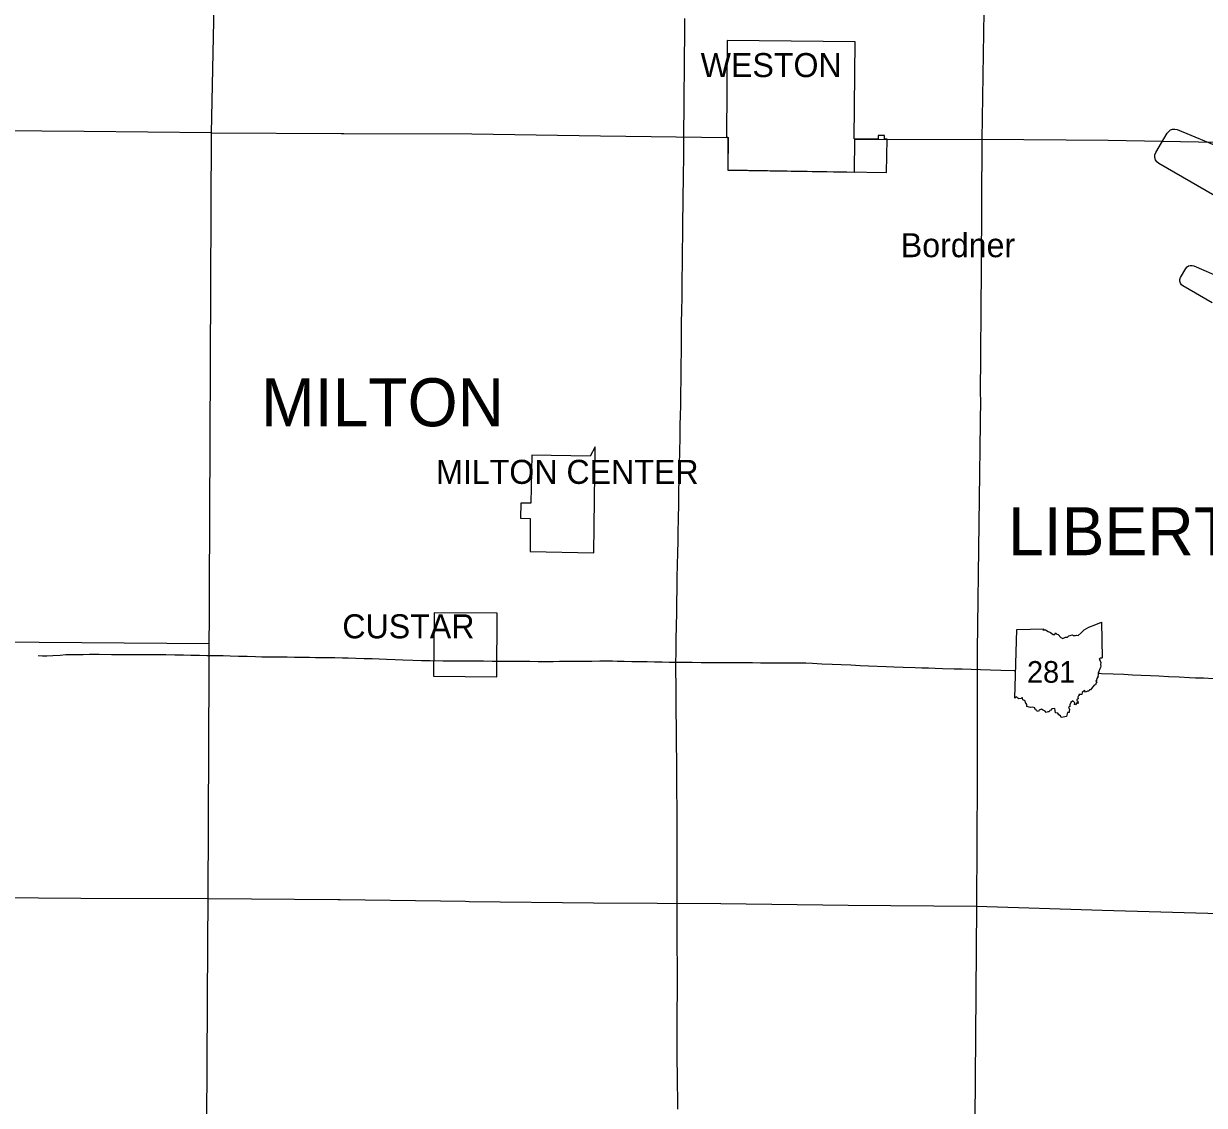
# Model space of a CAD drawing. Extents: x -232 to 448, y 619 to 1059.
# Drawn here: x 68.1 to 118.6, y 774.3 to 820.5 of the extents above; entities that cross this region are included whole.
import ezdxf

# ---------------------------------------------------------------- set-up
doc = ezdxf.new("R2010")
doc.units = 0
doc.layers.add('Default', color=7, linetype='Continuous')

msp = doc.modelspace()

# ---------------------------------------------------------------- linework, layer by layer
at = {"layer": 'Default'}
for p, q in [((104.623, 815.735), (104.617, 815.584)), ((104.9, 815.73), (104.623, 815.735)), ((104.897, 815.576), (104.9, 815.73)), ((104.617, 815.584), (103.599, 815.589)), ((105.003, 815.578), (104.897, 815.576)), ((104.979, 814.149), (105.003, 815.578)), ((110.457, 791.72), (110.539, 794.648)), ((110.457, 791.72), (110.539, 794.648))]:
    msp.add_line(p, q, dxfattribs=at)
for points in [[(109.26, 831.913), (109.194, 826.425), (109.132, 821.025), (109.053, 815.566)], [(76.168, 815.845), (76.27, 821.291)], [(96.36, 819.165), (96.361, 819.235), (96.366, 819.816), (96.37, 820.325), (96.373, 820.728)], [(103.636, 819.733), (98.172, 819.783), (98.153, 815.657)], [(103.599, 815.589), (103.636, 819.733)], [(96.326, 815.07), (96.329, 815.569), (96.332, 816.125), (96.337, 816.673), (96.345, 817.195), (96.347, 817.753), (96.354, 818.299), (96.355, 818.806), (96.36, 819.165)], [(76.168, 815.845), (70.724, 815.907), (65.304, 815.949), (59.876, 816.001), (54.446, 816.075), (54.399, 816.071), (49.027, 816.078), (48.986, 816.078), (43.453, 816.11)], [(76.015, 783.15), (76.168, 815.845)], [(76.168, 815.845), (81.699, 815.818), (81.812, 815.822), (87.28, 815.809), (92.763, 815.723), (98.167, 815.653), (98.218, 815.652), (98.2, 814.256), (103.614, 814.171), (103.632, 815.58), (109.053, 815.566)], [(98.153, 815.657), (98.21, 815.656)], [(98.21, 815.656), (98.21, 814.274)], [(120.275, 812.415), (116.605, 814.534), (116.52, 814.603), (116.46, 814.694), (116.432, 814.8), (116.438, 814.909), (116.477, 815.011), (116.955, 815.838), (117.099, 815.975), (117.194, 816.007), (117.294, 816.011), (117.391, 815.986), (121.228, 814.392)], [(109.053, 815.566), (109.022, 810.07), (108.982, 804.635), (108.986, 804.516), (108.919, 799.171), (108.846, 793.728), (108.845, 788.284), (108.821, 782.822)], [(141.903, 814.75), (138.372, 814.906), (136.423, 814.952), (130.937, 815.125), (125.356, 815.31), (119.857, 815.421), (114.444, 815.526), (109.053, 815.566)], [(96.308, 813.659), (96.309, 813.713), (96.313, 814.128), (96.32, 814.723), (96.326, 815.07)], [(98.21, 814.274), (104.979, 814.149)], [(95.988, 793.251), (95.995, 793.649), (96.004, 794.216), (96.013, 794.803), (96.024, 795.353), (96.033, 795.821), (96.043, 796.354), (96.048, 796.859), (96.061, 797.407), (96.069, 797.918), (96.078, 798.419), (96.086, 798.766), (96.097, 799.392), (96.109, 799.987), (96.118, 800.494), (96.128, 801.077), (96.141, 801.664), (96.153, 802.253), (96.164, 802.832), (96.173, 803.314), (96.183, 803.837), (96.195, 804.155), (96.198, 804.671), (96.208, 805.36), (96.214, 805.972), (96.224, 806.485), (96.23, 807.113), (96.234, 807.738), (96.242, 808.261), (96.252, 808.832), (96.254, 809.3), (96.26, 809.657), (96.265, 810.203), (96.273, 810.819), (96.278, 811.478), (96.287, 812.149), (96.297, 812.761), (96.303, 813.354), (96.308, 813.659)], [(118.887, 808.586), (117.633, 809.31), (117.569, 809.361), (117.525, 809.43), (117.504, 809.509), (117.508, 809.591), (117.537, 809.667), (117.765, 810.061), (117.812, 810.121), (117.874, 810.164), (117.946, 810.188), (118.022, 810.19), (118.095, 810.171), (119.276, 809.66)], [(92.33, 802.044), (89.838, 802.086), (89.799, 800.04), (89.368, 800.04), (89.356, 799.392), (89.768, 799.382), (89.766, 799.117), (89.768, 798.951), (89.764, 798.593), (89.768, 798.322), (89.76, 797.98)], [(89.76, 797.98), (92.485, 797.917), (92.542, 802.445)], [(92.542, 802.445), (92.33, 802.044)], [(85.667, 795.362), (85.646, 792.656)], [(85.646, 792.656), (88.341, 792.623), (88.358, 795.343)], [(88.358, 795.343), (85.667, 795.362)], [(110.539, 794.648), (111.675, 794.668), (111.657, 794.632), (111.765, 794.625), (111.879, 794.562), (111.975, 794.523), (112.093, 794.43), (112.163, 794.431), (112.193, 794.507), (112.247, 794.448), (112.311, 794.437), (112.422, 794.297), (112.513, 794.267), (112.623, 794.315), (112.705, 794.323), (112.765, 794.37), (112.921, 794.411), (112.964, 794.387), (113.047, 794.392), (113.088, 794.41), (113.16, 794.393), (113.287, 794.5), (113.417, 794.626), (113.618, 794.744), (113.918, 794.856), (114.155, 794.957), (114.189, 793.437)], [(110.539, 794.648), (111.675, 794.668), (111.657, 794.632), (111.765, 794.625), (111.879, 794.562), (111.975, 794.523), (112.093, 794.43), (112.163, 794.431), (112.193, 794.507), (112.247, 794.448), (112.311, 794.437), (112.422, 794.297), (112.513, 794.267), (112.623, 794.315), (112.705, 794.323), (112.765, 794.37), (112.921, 794.411), (112.964, 794.387), (113.047, 794.392), (113.088, 794.41), (113.16, 794.393), (113.287, 794.5), (113.417, 794.626), (113.618, 794.744), (113.918, 794.856), (114.155, 794.957), (114.189, 793.437)], [(59.717, 794.177), (76.066, 794.048)], [(68.765, 793.531), (68.946, 793.521), (69.124, 793.527), (69.39, 793.542), (69.694, 793.555), (69.947, 793.571), (70.165, 793.579), (70.34, 793.583), (70.677, 793.582), (70.955, 793.585), (71.37, 793.586), (71.889, 793.582), (72.377, 793.581), (72.847, 793.581), (73.333, 793.578), (73.758, 793.578), (74.217, 793.576), (74.594, 793.569), (74.972, 793.56), (75.273, 793.553), (75.648, 793.547), (75.968, 793.539), (76.269, 793.537), (76.665, 793.53), (76.96, 793.523), (77.313, 793.509), (77.686, 793.504), (78.034, 793.492), (78.313, 793.485), (78.373, 793.485)], [(78.373, 793.485), (78.574, 793.484), (78.828, 793.48), (78.861, 793.479)], [(78.861, 793.479), (79.095, 793.476), (79.392, 793.473), (79.71, 793.468), (79.726, 793.467)], [(79.726, 793.467), (80.015, 793.463), (80.348, 793.461), (80.602, 793.455), (80.881, 793.453), (81.074, 793.449)], [(81.074, 793.449), (81.123, 793.447), (81.42, 793.443), (81.748, 793.439), (81.996, 793.431), (82.328, 793.422), (82.685, 793.414), (83.025, 793.402), (83.322, 793.389), (83.636, 793.377), (83.999, 793.363), (84.327, 793.351), (84.759, 793.335), (85.124, 793.32), (85.499, 793.316), (86.047, 793.312), (86.486, 793.312), (86.916, 793.306), (87.353, 793.304), (87.774, 793.303), (88.145, 793.298), (88.547, 793.297), (88.943, 793.294), (89.353, 793.291), (89.753, 793.288), (90.11, 793.286), (90.472, 793.281), (90.749, 793.281), (91.018, 793.287), (91.363, 793.288), (91.712, 793.29), (92.023, 793.293), (92.399, 793.299), (92.742, 793.301), (93.058, 793.302), (93.283, 793.305), (93.474, 793.299), (93.781, 793.296), (94.107, 793.286), (94.45, 793.278), (94.755, 793.275), (95.081, 793.27), (95.399, 793.262), (95.707, 793.255), (95.988, 793.251)], [(96.047, 777.004), (96.046, 777.361), (96.045, 777.939), (96.048, 778.461), (96.05, 779.048), (96.05, 779.447), (96.052, 780.004), (96.052, 780.323), (96.046, 781.069), (96.044, 781.835), (96.045, 782.342), (96.04, 783.03), (96.044, 783.72), (96.042, 784.264), (96.042, 784.708), (96.04, 785.242), (96.039, 785.798), (96.035, 786.256), (96.037, 786.689), (96.036, 787.176), (96.033, 787.597), (96.031, 787.948), (96.029, 788.466), (96.024, 789.129), (96.017, 789.645), (96.013, 790.072), (96.008, 790.507), (96.002, 791.109), (95.998, 791.585), (95.995, 791.994), (95.994, 792.366), (95.987, 792.787), (95.984, 793.103), (95.988, 793.251)], [(95.988, 793.251), (96.295, 793.246), (96.685, 793.247), (97.072, 793.242), (97.405, 793.241), (97.698, 793.238), (98.045, 793.238), (98.387, 793.235), (98.699, 793.232), (99.035, 793.232), (99.261, 793.231), (99.595, 793.227), (99.958, 793.227), (100.288, 793.226), (100.586, 793.223), (101.047, 793.221), (101.533, 793.218)], [(101.533, 793.218), (101.816, 793.205), (102.224, 793.185), (102.665, 793.167), (103.05, 793.148), (103.462, 793.132), (103.857, 793.115), (104.216, 793.098), (104.958, 793.067), (105.296, 793.051), (105.689, 793.036), (106.203, 793.016), (106.494, 793.009), (106.769, 793.002), (107.056, 792.993), (107.372, 792.986), (107.873, 792.971), (108.216, 792.96), (108.589, 792.949), (108.987, 792.934), (109.414, 792.925), (109.86, 792.914), (110.435, 792.898), (110.503, 792.896)], [(114.189, 793.437), (114.154, 793.415), (114.1, 793.425), (114.063, 793.383), (114.108, 793.312), (114.13, 793.237), (114.111, 793.154), (114.13, 793.085), (114.117, 793.028), (114.083, 792.971), (114.071, 792.917), (114.042, 792.86), (114.044, 792.828), (114.016, 792.803), (114.021, 792.707), (114.007, 792.655), (114.012, 792.609), (113.967, 792.597), (113.977, 792.56), (113.949, 792.531), (113.955, 792.481), (113.923, 792.449), (113.954, 792.385), (113.929, 792.365), (113.908, 792.288), (113.85, 792.272), (113.734, 792.13), (113.694, 792.076), (113.648, 792.063), (113.623, 792.008), (113.566, 792.008), (113.481, 791.97), (113.426, 792.035), (113.329, 791.956), (113.318, 791.865), (113.196, 791.868), (113.2, 791.822), (113.173, 791.808), (113.148, 791.762), (113.163, 791.68), (113.105, 791.659), (113.112, 791.611), (113.149, 791.582), (113.165, 791.491), (113.104, 791.509), (113.055, 791.432), (113.003, 791.45), (113.02, 791.515), (112.934, 791.594), (112.852, 791.531), (112.809, 791.431), (112.808, 791.363), (112.747, 791.323), (112.787, 791.227), (112.779, 791.162), (112.781, 791.1), (112.704, 791.102), (112.658, 790.934)], [(114.189, 793.437), (114.154, 793.415), (114.1, 793.425), (114.063, 793.383), (114.108, 793.312), (114.13, 793.237), (114.111, 793.154), (114.13, 793.085), (114.117, 793.028), (114.083, 792.971), (114.071, 792.917), (114.042, 792.86), (114.044, 792.828), (114.016, 792.803), (114.021, 792.707), (114.007, 792.655), (114.012, 792.609), (113.967, 792.597), (113.977, 792.56), (113.949, 792.531), (113.955, 792.481), (113.923, 792.449), (113.954, 792.385), (113.929, 792.365), (113.908, 792.288), (113.85, 792.272), (113.734, 792.13), (113.694, 792.076), (113.648, 792.063), (113.623, 792.008), (113.566, 792.008), (113.481, 791.97), (113.426, 792.035), (113.329, 791.956), (113.318, 791.865), (113.196, 791.868), (113.2, 791.822), (113.173, 791.808), (113.148, 791.762), (113.163, 791.68), (113.105, 791.659), (113.112, 791.611), (113.149, 791.582), (113.165, 791.491), (113.104, 791.509), (113.055, 791.432), (113.003, 791.45), (113.02, 791.515), (112.934, 791.594), (112.852, 791.531), (112.809, 791.431), (112.808, 791.363), (112.747, 791.323), (112.787, 791.227), (112.779, 791.162), (112.781, 791.1), (112.704, 791.102), (112.658, 790.934)], [(114.059, 792.775), (114.154, 792.771), (114.663, 792.75), (115.11, 792.732), (115.483, 792.716), (115.857, 792.697), (116.245, 792.678), (116.608, 792.662), (117.014, 792.641), (117.478, 792.619), (117.913, 792.601), (118.172, 792.587), (118.514, 792.577), (118.923, 792.56)], [(112.658, 790.934), (112.526, 790.901), (112.433, 790.882), (112.401, 790.959), (112.335, 790.999), (112.292, 791.076), (112.198, 791.086), (112.175, 791.192), (112.165, 791.278), (112.036, 791.256), (112, 791.204), (111.954, 791.19), (111.928, 791.137), (111.865, 791.133), (111.798, 791.108), (111.754, 791.16), (111.644, 791.212), (111.595, 791.238), (111.492, 791.197), (111.47, 791.147), (111.387, 791.169), (111.368, 791.224), (111.318, 791.241), (111.307, 791.299), (111.201, 791.33), (111.12, 791.318), (110.976, 791.365), (110.968, 791.441), (110.919, 791.535), (110.893, 791.6), (110.803, 791.649), (110.784, 791.727), (110.755, 791.724), (110.729, 791.693), (110.628, 791.679), (110.588, 791.71), (110.531, 791.764), (110.457, 791.72)], [(112.658, 790.934), (112.526, 790.901), (112.433, 790.882), (112.401, 790.959), (112.335, 790.999), (112.292, 791.076), (112.198, 791.086), (112.175, 791.192), (112.165, 791.278), (112.036, 791.256), (112, 791.204), (111.954, 791.19), (111.928, 791.137), (111.865, 791.133), (111.798, 791.108), (111.754, 791.16), (111.644, 791.212), (111.595, 791.238), (111.492, 791.197), (111.47, 791.147), (111.387, 791.169), (111.368, 791.224), (111.318, 791.241), (111.307, 791.299), (111.201, 791.33), (111.12, 791.318), (110.976, 791.365), (110.968, 791.441), (110.919, 791.535), (110.893, 791.6), (110.803, 791.649), (110.784, 791.727), (110.755, 791.724), (110.729, 791.693), (110.628, 791.679), (110.588, 791.71), (110.531, 791.764), (110.457, 791.72)], [(76.015, 783.15), (70.577, 783.165), (65.14, 783.201), (59.652, 783.191), (54.113, 783.24), (48.623, 783.305), (43.396, 783.369)], [(75.834, 750.532), (76.007, 781.259), (76.015, 783.15)], [(108.821, 782.822), (103.347, 782.858), (97.913, 782.939), (92.468, 782.966), (87.167, 783.026), (87.011, 783.029), (81.659, 783.1), (81.552, 783.099), (76.015, 783.15)], [(108.821, 782.822), (108.779, 777.282), (108.742, 771.921), (108.706, 766.405), (108.69, 760.973), (108.682, 755.645), (108.58, 750.206)], [(141.496, 781.792), (135.927, 781.939), (130.57, 782.12), (125.187, 782.267), (125.191, 782.442), (119.694, 782.492), (114.189, 782.65), (108.821, 782.822)], [(96.047, 776.734), (96.047, 777.004)], [(96.074, 774.171), (96.07, 774.67), (96.06, 775.177), (96.05, 775.652), (96.049, 776.261), (96.047, 776.734)]]:
    msp.add_lwpolyline(points, dxfattribs=at)

# ---------------------------------------------------------------- texts
for s, height, p in [('WESTON', 1.026, (97.044, 818.227)), ('Bordner                    ', 1.026, (105.59, 810.538)), ('MILTON', 2.052, (78.284, 803.319)), ('MILTON CENTER', 1.026, (85.751, 800.862)), ('LIBERTY', 2.052, (110.166, 797.815)), ('CUSTAR', 1.026, (81.747, 794.268)), ('281', 0.9234, (110.976, 792.373))]:
    msp.add_text(s, height=height, dxfattribs=at).set_placement(p)

doc.saveas('drawing.dxf')
